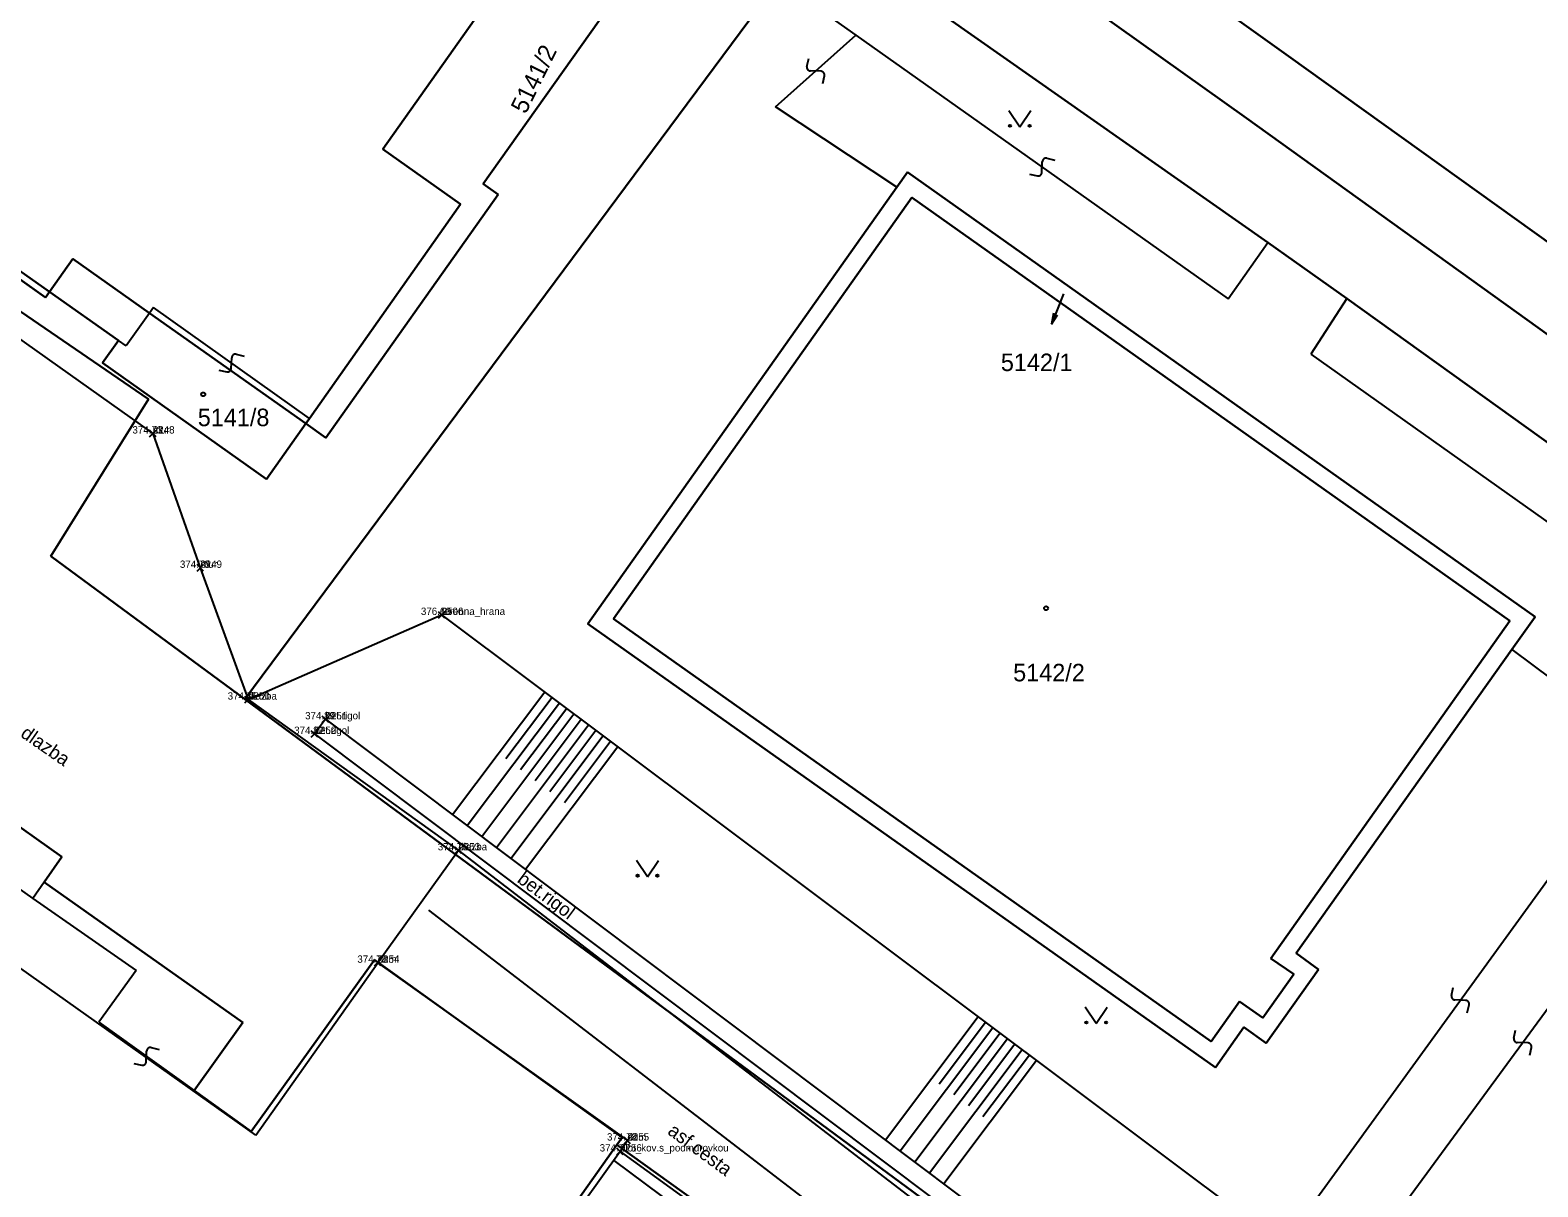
# Model space of a CAD drawing. Extents: x -400488 to -400124, y -1251493 to -1251223.
# Drawn here: x -400324.23 to -400282.93, y -1251328.7 to -1251297.01 of the extents above; entities that cross this region are included whole.
import ezdxf

# ---------------------------------------------------------------- set-up
doc = ezdxf.new("R2010")
doc.units = 0
for name, color, linetype in [('Level 20', 7, 'Continuous'), ('Level 21', 7, 'Continuous'), ('Level 22', 7, 'Continuous'), ('Level 23', 7, 'Continuous'), ('Level 31', 7, 'Continuous'), ('Level 32', 7, 'Continuous'), ('Level 34', 7, 'Continuous'), ('Level 35', 7, 'Continuous'), ('Level 36', 7, 'Continuous'), ('Level 63', 7, 'Continuous')]:
    doc.layers.add(name, color=color, linetype=linetype)

msp = doc.modelspace()

# ---------------------------------------------------------------- linework, layer by layer
at = {"layer": 'Level 20'}
for p, q in [((-400320.958, -1251308.148), (-400320.782, -1251307.972)), ((-400320.782, -1251308.148), (-400320.958, -1251307.972)), ((-400319.658, -1251311.828), (-400319.482, -1251311.652)), ((-400319.482, -1251311.828), (-400319.658, -1251311.652)), ((-400313.048, -1251313.118), (-400312.872, -1251312.942)), ((-400312.872, -1251313.118), (-400313.048, -1251312.942)), ((-400318.348, -1251315.438), (-400318.172, -1251315.262)), ((-400318.172, -1251315.438), (-400318.348, -1251315.262)), ((-400316.228, -1251315.978), (-400316.052, -1251315.802)), ((-400316.052, -1251315.978), (-400316.228, -1251315.802)), ((-400316.528, -1251316.378), (-400316.352, -1251316.202)), ((-400316.352, -1251316.378), (-400316.528, -1251316.202)), ((-400312.588, -1251319.568), (-400312.412, -1251319.392)), ((-400312.412, -1251319.568), (-400312.588, -1251319.392)), ((-400314.798, -1251322.648), (-400314.622, -1251322.472)), ((-400314.622, -1251322.648), (-400314.798, -1251322.472)), ((-400307.958, -1251327.518), (-400307.782, -1251327.342)), ((-400307.782, -1251327.518), (-400307.958, -1251327.342)), ((-400308.158, -1251327.818), (-400307.982, -1251327.642)), ((-400307.982, -1251327.818), (-400308.158, -1251327.642))]:
    msp.add_line(p, q, dxfattribs=at)
at = {"layer": 'Level 31'}
for p, q in [((-400310.134, -1251315.148), (-400312.658, -1251318.507)), ((-400309.733, -1251315.447), (-400312.258, -1251318.807)), ((-400309.933, -1251315.297), (-400311.196, -1251316.977)), ((-400309.333, -1251315.747), (-400311.858, -1251319.107)), ((-400309.533, -1251315.597), (-400310.796, -1251317.277)), ((-400309.133, -1251315.897), (-400310.396, -1251317.577)), ((-400308.933, -1251316.047), (-400311.459, -1251319.408)), ((-400308.533, -1251316.347), (-400311.059, -1251319.708)), ((-400308.733, -1251316.197), (-400309.996, -1251317.877)), ((-400308.133, -1251316.647), (-400310.659, -1251320.009)), ((-400308.333, -1251316.497), (-400309.596, -1251318.178)), ((-400298.26, -1251324.043), (-400300.797, -1251327.42)), ((-400298.06, -1251324.193), (-400299.329, -1251325.882)), ((-400297.86, -1251324.343), (-400300.397, -1251327.72)), ((-400297.459, -1251324.643), (-400299.998, -1251328.021)), ((-400297.66, -1251324.493), (-400298.929, -1251326.182)), ((-400297.059, -1251324.943), (-400299.598, -1251328.321)), ((-400297.259, -1251324.793), (-400298.529, -1251326.482)), ((-400296.659, -1251325.242), (-400299.198, -1251328.621)), ((-400296.859, -1251325.093), (-400298.129, -1251326.782))]:
    msp.add_line(p, q, dxfattribs=at)
for points in [[(-400319.57, -1251311.74), (-400318.26, -1251315.35), (-400312.5, -1251319.48), (-400314.71, -1251322.56)], [(-400318.26, -1251315.35), (-400312.96, -1251313.03), (-400288.36, -1251331.46), (-400266.982, -1251349.498)], [(-400316.14, -1251315.89), (-400316.44, -1251316.29), (-400297.85, -1251330.26), (-400287.82, -1251337.3), (-400269.11, -1251350.68), (-400268.97, -1251350.75), (-400268.595, -1251350.721), (-400268.22, -1251350.66), (-400265.46, -1251349.31), (-400264.73, -1251348.69)], [(-400316.14, -1251315.89), (-400297.556, -1251329.855), (-400287.531, -1251336.892), (-400268.865, -1251350.24), (-400268.655, -1251350.224), (-400268.373, -1251350.178), (-400265.736, -1251348.888), (-400265.364, -1251348.599), (-400265.054, -1251348.309), (-400262.095, -1251344.059)]]:
    msp.add_lwpolyline(points, dxfattribs=at)
at = {"layer": 'Level 32'}
for points in [[(-400312.5, -1251319.48), (-400297.6, -1251330.92), (-400269.6, -1251350.67), (-400269.57, -1251350.69), (-400268.48, -1251351.39), (-400267.759, -1251351.812), (-400266.88, -1251352.23), (-400265.72, -1251352.64), (-400264.993, -1251352.795), (-400264.19, -1251352.85), (-400263.653, -1251352.732), (-400263.2, -1251352.53), (-400262.601, -1251352.1), (-400262.03, -1251351.63), (-400261.48, -1251350.91)], [(-400313.317, -1251321.122), (-400298.667, -1251332.37), (-400270.618, -1251352.155), (-400270.556, -1251352.196), (-400267.742, -1251354.003)]]:
    msp.add_lwpolyline(points, dxfattribs=at)
at = {"layer": 'Level 34'}
for points in [[(-400318.045, -1251327.281), (-400335.362, -1251315.009), (-400331.92, -1251310.33)], [(-400318.045, -1251327.281), (-400314.71, -1251322.56), (-400307.87, -1251327.43), (-400308.07, -1251327.73), (-400312.65, -1251334.13)]]:
    msp.add_lwpolyline(points, dxfattribs=at)
at = {"layer": 'Level 35'}
for points in [[(-400338.97, -1251298.5), (-400337.4, -1251296.33), (-400320.87, -1251308.06), (-400319.57, -1251311.74)], [(-400308.07, -1251327.73), (-400306.34, -1251328.98)], [(-400308.245, -1251327.974), (-400306.52, -1251329.26), (-400306.34, -1251328.98)]]:
    msp.add_lwpolyline(points, dxfattribs=at)
at = {"layer": 'Level 36'}
for p, q in [((-400307.319, -1251320.204), (-400307.619, -1251319.754)), ((-400307.319, -1251320.204), (-400307.019, -1251319.754)), ((-400295.026, -1251324.227), (-400295.326, -1251323.777)), ((-400295.026, -1251324.227), (-400294.726, -1251323.777))]:
    msp.add_line(p, q, dxfattribs=at)
for centre in [(-400307.589, -1251320.174), (-400307.049, -1251320.174), (-400295.296, -1251324.197), (-400294.756, -1251324.197)]:
    msp.add_circle(centre, 0.03, dxfattribs=at)
at = {"layer": 'Level 63'}
for p, q in [((-400310.49, -1251282.91), (-400289.76, -1251297.72)), ((-400289.76, -1251297.72), (-400310.49, -1251282.91)), ((-400290.91, -1251299.42), (-400311.69, -1251284.59)), ((-400311.69, -1251284.59), (-400290.91, -1251299.42)), ((-400302.68, -1251294.16), (-400290.33, -1251302.83)), ((-400290.33, -1251302.83), (-400302.68, -1251294.16)), ((-400314.57, -1251300.27), (-400310.56, -1251294.61)), ((-400310.56, -1251294.61), (-400314.57, -1251300.27)), ((-400318.35, -1251315.34), (-400303.73, -1251295.65)), ((-400303.73, -1251295.65), (-400318.35, -1251315.34)), ((-400303.73, -1251295.65), (-400301.61, -1251297.15)), ((-400311.82, -1251301.22), (-400308.1, -1251295.98)), ((-400308.1, -1251295.98), (-400311.82, -1251301.22)), ((-400303.81, -1251299.11), (-400301.61, -1251297.15)), ((-400301.61, -1251297.15), (-400291.41, -1251304.37)), ((-400302.951, -1251298.003), (-400302.903, -1251297.785)), ((-400289.76, -1251297.72), (-400267.74, -1251313.52)), ((-400267.74, -1251313.52), (-400289.76, -1251297.72)), ((-400302.563, -1251298.136), (-400302.857, -1251298.124)), ((-400333.8, -1251298.36), (-400320.99, -1251307.12)), ((-400320.99, -1251307.12), (-400333.8, -1251298.36)), ((-400302.517, -1251298.475), (-400302.469, -1251298.257)), ((-400300.49, -1251301.31), (-400303.81, -1251299.11)), ((-400297.42, -1251299.21), (-400297.12, -1251299.66)), ((-400297.12, -1251299.66), (-400296.82, -1251299.21)), ((-400271.92, -1251313.08), (-400290.91, -1251299.42)), ((-400290.91, -1251299.42), (-400271.92, -1251313.08)), ((-400329.71, -1251300.16), (-400323.81, -1251304.33)), ((-400323.81, -1251304.33), (-400329.71, -1251300.16)), ((-400329.6, -1251300.01), (-400323.7, -1251304.18)), ((-400323.7, -1251304.18), (-400329.6, -1251300.01)), ((-400312.44, -1251301.78), (-400314.57, -1251300.27)), ((-400314.57, -1251300.27), (-400312.44, -1251301.78)), ((-400296.516, -1251300.907), (-400296.504, -1251300.613)), ((-400296.383, -1251300.519), (-400296.165, -1251300.567)), ((-400300.2, -1251300.9), (-400300.49, -1251301.31)), ((-400300.49, -1251301.31), (-400300.2, -1251300.9)), ((-400283, -1251313.08), (-400300.2, -1251300.9)), ((-400300.2, -1251300.9), (-400283, -1251313.08)), ((-400296.855, -1251300.953), (-400296.637, -1251301.001)), ((-400316.13, -1251308.18), (-400311.41, -1251301.51)), ((-400311.41, -1251301.51), (-400316.13, -1251308.18)), ((-400311.41, -1251301.51), (-400311.82, -1251301.22)), ((-400311.82, -1251301.22), (-400311.41, -1251301.51)), ((-400300.49, -1251301.31), (-400308.95, -1251313.27)), ((-400308.95, -1251313.27), (-400300.49, -1251301.31)), ((-400316.58, -1251307.65), (-400312.44, -1251301.78)), ((-400312.44, -1251301.78), (-400316.58, -1251307.65)), ((-400308.25, -1251313.14), (-400300.08, -1251301.59)), ((-400300.08, -1251301.59), (-400308.25, -1251313.14)), ((-400300.08, -1251301.59), (-400283.7, -1251313.19)), ((-400283.7, -1251313.19), (-400300.08, -1251301.59)), ((-400291.41, -1251304.37), (-400290.33, -1251302.83)), ((-400290.33, -1251302.83), (-400288.16, -1251304.36)), ((-400288.16, -1251304.36), (-400290.33, -1251302.83)), ((-400323.7, -1251304.18), (-400323.06, -1251303.27)), ((-400323.06, -1251303.27), (-400323.7, -1251304.18)), ((-400323.06, -1251303.27), (-400320.96, -1251304.76)), ((-400320.96, -1251304.76), (-400323.06, -1251303.27)), ((-400323.81, -1251304.33), (-400323.7, -1251304.18)), ((-400323.7, -1251304.18), (-400323.81, -1251304.33)), ((-400323.7, -1251304.18), (-400321.81, -1251305.51)), ((-400321.81, -1251305.51), (-400323.7, -1251304.18)), ((-400295.92, -1251304.23), (-400296.256, -1251305.065)), ((-400288.16, -1251304.36), (-400289.15, -1251305.89)), ((-400288.16, -1251304.36), (-400263.64, -1251321.96)), ((-400263.64, -1251321.96), (-400288.16, -1251304.36)), ((-400320.96, -1251304.76), (-400321.6, -1251305.66)), ((-400320.85, -1251304.61), (-400320.96, -1251304.76)), ((-400320.96, -1251304.76), (-400316.68, -1251307.79)), ((-400316.68, -1251307.79), (-400320.96, -1251304.76)), ((-400316.58, -1251307.65), (-400320.85, -1251304.61)), ((-400296.2, -1251304.764), (-400296.256, -1251305.065)), ((-400296.256, -1251305.065), (-400296.088, -1251304.809)), ((-400321.81, -1251305.51), (-400322.25, -1251306.12)), ((-400322.25, -1251306.12), (-400321.81, -1251305.51)), ((-400321.6, -1251305.66), (-400321.81, -1251305.51)), ((-400318.721, -1251306.277), (-400318.709, -1251305.983)), ((-400318.588, -1251305.889), (-400318.37, -1251305.937)), ((-400289.15, -1251305.89), (-400264.66, -1251323.25)), ((-400322.25, -1251306.12), (-400317.76, -1251309.31)), ((-400317.76, -1251309.31), (-400322.25, -1251306.12)), ((-400319.06, -1251306.323), (-400318.842, -1251306.371)), ((-400320.99, -1251307.12), (-400323.66, -1251311.42)), ((-400323.66, -1251311.42), (-400320.99, -1251307.12)), ((-400316.68, -1251307.79), (-400316.58, -1251307.65)), ((-400316.58, -1251307.65), (-400316.68, -1251307.79)), ((-400317.76, -1251309.31), (-400316.68, -1251307.79)), ((-400316.68, -1251307.79), (-400317.76, -1251309.31)), ((-400316.68, -1251307.79), (-400316.13, -1251308.18)), ((-400316.13, -1251308.18), (-400316.68, -1251307.79)), ((-400323.66, -1251311.42), (-400318.35, -1251315.34)), ((-400318.35, -1251315.34), (-400323.66, -1251311.42)), ((-400283.64, -1251313.98), (-400283, -1251313.08)), ((-400283, -1251313.08), (-400283.64, -1251313.98)), ((-400308.95, -1251313.27), (-400291.76, -1251325.43)), ((-400291.76, -1251325.43), (-400308.95, -1251313.27)), ((-400291.88, -1251324.72), (-400308.25, -1251313.14)), ((-400308.25, -1251313.14), (-400291.88, -1251324.72)), ((-400283.7, -1251313.19), (-400290.24, -1251322.44)), ((-400290.24, -1251322.44), (-400283.7, -1251313.19)), ((-400289.55, -1251322.3), (-400283.64, -1251313.98)), ((-400283.64, -1251313.98), (-400289.55, -1251322.3)), ((-400283.64, -1251313.98), (-400280.04, -1251316.67)), ((-400297.73, -1251330.54), (-400318.35, -1251315.34)), ((-400318.35, -1251315.34), (-400297.73, -1251330.54)), ((-400290.07, -1251330.5), (-400280.04, -1251316.67)), ((-400326.53, -1251317.41), (-400323.36, -1251319.66)), ((-400323.36, -1251319.66), (-400326.53, -1251317.41)), ((-400278.27, -1251317.84), (-400288.42, -1251331.66)), ((-400327.34, -1251318.55), (-400324.16, -1251320.8)), ((-400323.36, -1251319.66), (-400323.85, -1251320.35)), ((-400323.85, -1251320.35), (-400323.36, -1251319.66)), ((-400323.85, -1251320.35), (-400324.16, -1251320.8)), ((-400323.85, -1251320.35), (-400318.4, -1251324.2)), ((-400318.4, -1251324.2), (-400323.85, -1251320.35)), ((-400324.16, -1251320.8), (-400321.33, -1251322.77)), ((-400318.18, -1251327.18), (-400314.8, -1251322.48)), ((-400314.8, -1251322.48), (-400318.18, -1251327.18)), ((-400314.8, -1251322.48), (-400308.01, -1251327.35)), ((-400308.01, -1251327.35), (-400314.8, -1251322.48)), ((-400290.24, -1251322.44), (-400289.61, -1251322.87)), ((-400289.61, -1251322.87), (-400290.24, -1251322.44)), ((-400288.94, -1251322.74), (-400289.55, -1251322.3)), ((-400289.55, -1251322.3), (-400288.94, -1251322.74)), ((-400321.33, -1251322.77), (-400322.35, -1251324.19)), ((-400289.61, -1251322.87), (-400290.46, -1251324.07)), ((-400290.46, -1251324.07), (-400289.61, -1251322.87)), ((-400290.37, -1251324.76), (-400288.94, -1251322.74)), ((-400288.94, -1251322.74), (-400290.37, -1251324.76)), ((-400285.296, -1251323.458), (-400285.248, -1251323.24)), ((-400291.1, -1251323.62), (-400291.88, -1251324.72)), ((-400291.88, -1251324.72), (-400291.1, -1251323.62)), ((-400290.46, -1251324.07), (-400291.1, -1251323.62)), ((-400291.1, -1251323.62), (-400290.46, -1251324.07)), ((-400284.908, -1251323.591), (-400285.202, -1251323.579)), ((-400284.862, -1251323.93), (-400284.814, -1251323.712)), ((-400322.35, -1251324.19), (-400319.74, -1251326.06)), ((-400318.4, -1251324.2), (-400319.74, -1251326.06)), ((-400319.74, -1251326.06), (-400318.4, -1251324.2)), ((-400291.76, -1251325.43), (-400290.98, -1251324.32)), ((-400290.98, -1251324.32), (-400291.76, -1251325.43)), ((-400290.98, -1251324.32), (-400290.37, -1251324.76)), ((-400290.37, -1251324.76), (-400290.98, -1251324.32)), ((-400283.586, -1251324.623), (-400283.538, -1251324.405)), ((-400321.051, -1251325.272), (-400321.039, -1251324.978)), ((-400320.918, -1251324.884), (-400320.7, -1251324.932)), ((-400283.198, -1251324.756), (-400283.492, -1251324.744)), ((-400283.152, -1251325.095), (-400283.104, -1251324.877)), ((-400321.39, -1251325.318), (-400321.172, -1251325.366)), ((-400319.74, -1251326.06), (-400318.18, -1251327.18)), ((-400318.18, -1251327.18), (-400319.74, -1251326.06)), ((-400312.75, -1251334.01), (-400308.16, -1251327.55)), ((-400308.16, -1251327.55), (-400312.75, -1251334.01)), ((-400308.01, -1251327.35), (-400308.16, -1251327.55)), ((-400308.16, -1251327.55), (-400308.01, -1251327.35)), ((-400308.16, -1251327.55), (-400270.88, -1251354.21)), ((-400270.88, -1251354.21), (-400308.16, -1251327.55))]:
    msp.add_line(p, q, dxfattribs=at)
for centre, radius in [((-400297.39, -1251299.63), 0.03), ((-400296.85, -1251299.63), 0.03), ((-400319.49, -1251306.986), 0.054), ((-400296.4, -1251312.846), 0.054)]:
    msp.add_circle(centre, radius, dxfattribs=at)
for centre, start, end in [((-400302.853, -1251298.024), 167.7527, 267.7631), ((-400302.567, -1251298.236), 347.753, 87.7631), ((-400296.404, -1251300.617), 77.7527, 177.7631), ((-400296.616, -1251300.903), 257.753, 357.7631), ((-400318.609, -1251305.987), 77.7527, 177.7631), ((-400318.821, -1251306.273), 257.753, 357.7631), ((-400285.198, -1251323.479), 167.7527, 267.7631), ((-400284.912, -1251323.691), 347.753, 87.7631), ((-400283.488, -1251324.644), 167.7527, 267.7631), ((-400320.939, -1251324.982), 77.7527, 177.7631), ((-400283.202, -1251324.856), 347.753, 87.7631), ((-400321.151, -1251325.268), 257.753, 357.7631)]:
    msp.add_arc(centre, 0.1, start, end, dxfattribs=at)

# ---------------------------------------------------------------- texts
at = {"layer": 'Level 21'}
for s, p in [('2248', (-400320.87, -1251308.06)), ('2249', (-400319.57, -1251311.74)), ('2506', (-400312.96, -1251313.03)), ('2250', (-400318.26, -1251315.35)), ('2251', (-400316.14, -1251315.89)), ('2252', (-400316.44, -1251316.29)), ('2253', (-400312.5, -1251319.48)), ('2254', (-400314.71, -1251322.56)), ('2256', (-400308.07, -1251327.73)), ('2255', (-400307.87, -1251327.43))]:
    msp.add_text(s, height=0.2, dxfattribs=at).set_placement(p)
at = {"layer": 'Level 22'}
for s, p in [('mur', (-400320.87, -1251308.06)), ('mur', (-400319.57, -1251311.74)), ('terenna_hrana', (-400312.96, -1251313.03)), ('dlazba', (-400318.26, -1251315.35)), ('bet.rigol', (-400316.14, -1251315.89)), ('bet.rigol', (-400316.44, -1251316.29)), ('dlazba', (-400312.5, -1251319.48)), ('dom', (-400314.71, -1251322.56)), ('plot_kov.s_podmurovkou', (-400308.07, -1251327.73)), ('dom', (-400307.87, -1251327.43))]:
    msp.add_text(s, height=0.2, dxfattribs=at).set_placement(p)
at = {"layer": 'Level 23'}
for s, p in [('374.73', (-400321.428, -1251308.06)), ('374.78', (-400320.128, -1251311.74)), ('376.60', (-400313.526, -1251313.03)), ('374.75', (-400318.819, -1251315.35)), ('374.89', (-400316.698, -1251315.89)), ('374.82', (-400316.998, -1251316.29)), ('374.76', (-400313.063, -1251319.48)), ('374.78', (-400315.268, -1251322.56)), ('374.77', (-400308.628, -1251327.73)), ('374.78', (-400308.428, -1251327.43))]:
    msp.add_text(s, height=0.2, dxfattribs=at).set_placement(p)
at = {"layer": 'Level 31'}
for s, rotation, p in [('dlazba', 325.2178, (-400324.52, -1251316.347)), ('bet.rigol', 323.3813, (-400310.916, -1251320.331))]:
    msp.add_text(s, height=0.375, rotation=rotation, dxfattribs=at).set_placement(p)
at = {"layer": 'Level 32'}
msp.add_text('asf.cesta', height=0.375, rotation=323.6458, dxfattribs=at).set_placement((-400306.794, -1251327.233))
at = {"layer": 'Level 63'}
msp.add_text('5141/2', height=0.48, rotation=63.79, dxfattribs=at).set_placement((-400310.656, -1251299.33))
for s, p in [('5142/1', (-400297.639, -1251306.35)), ('5141/8', (-400319.639, -1251307.859)), ('5142/2', (-400297.302, -1251314.85))]:
    msp.add_text(s, height=0.48, dxfattribs=at).set_placement(p)

doc.saveas('drawing.dxf')
